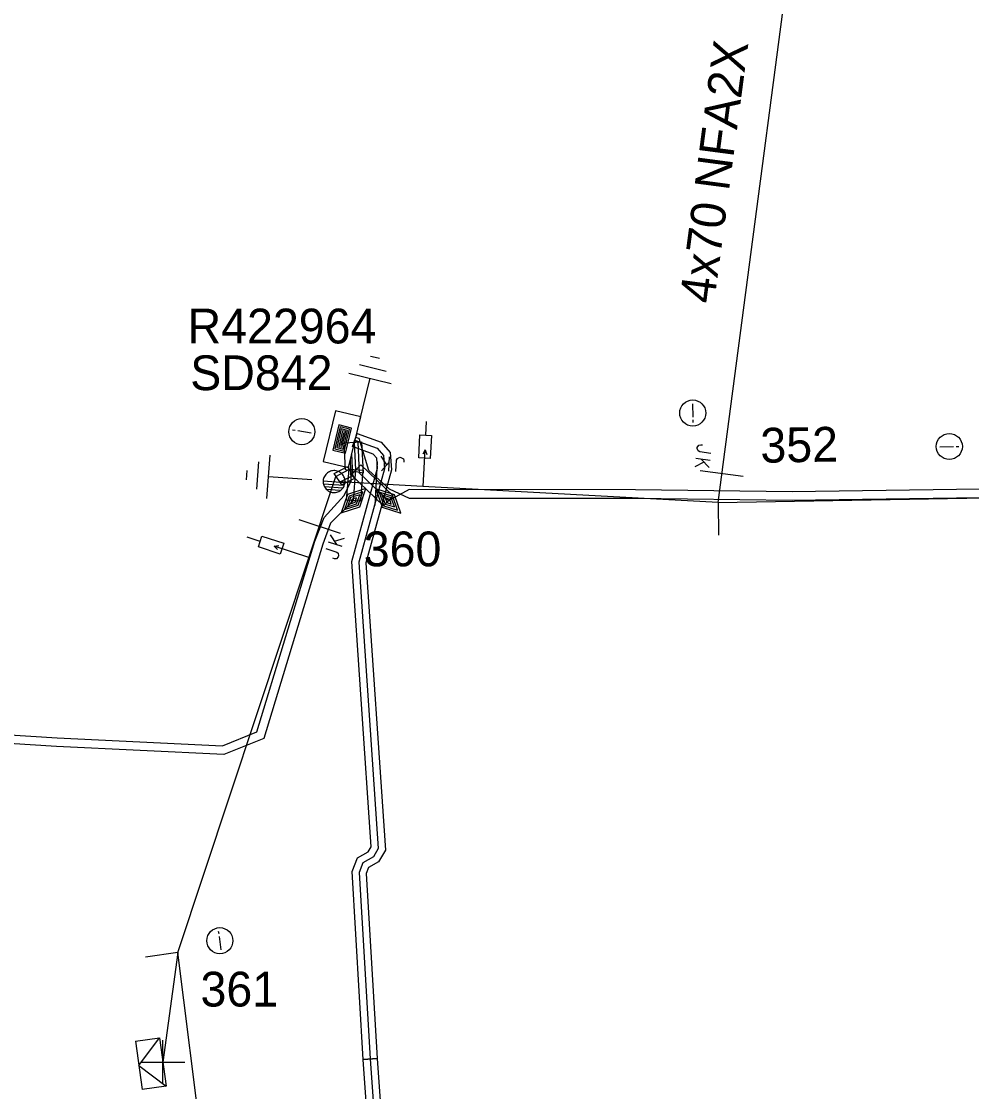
# Model space of a CAD drawing. Extents: x -540466 to -537383, y -1184038 to -1179972.
# Drawn here: x -538053.92 to -538026.6, y -1180873.24 to -1180842.47 of the extents above; entities that cross this region are included whole.
import ezdxf

# ---------------------------------------------------------------- set-up
doc = ezdxf.new("R2010")
doc.units = 0
for name, color, linetype in [('Vrstva 1', 7, 'Continuous'), ('Vrstva 10', 7, 'Continuous'), ('Vrstva 13', 7, 'Continuous'), ('Vrstva 14', 7, 'Continuous'), ('Vrstva 15', 7, 'Continuous'), ('Vrstva 16', 7, 'Continuous'), ('Vrstva 18', 7, 'Continuous'), ('Vrstva 19', 7, 'Continuous'), ('Vrstva 2', 7, 'Continuous'), ('Vrstva 20', 7, 'Continuous'), ('Vrstva 28', 7, 'Continuous'), ('Vrstva 29', 7, 'Continuous'), ('Vrstva 30', 7, 'Continuous'), ('Vrstva 31', 7, 'Continuous'), ('Vrstva 34', 7, 'Continuous'), ('Vrstva 36', 7, 'Continuous'), ('Vrstva 4', 7, 'Continuous'), ('Vrstva 5', 7, 'Continuous'), ('Vrstva 50', 7, 'Continuous'), ('Vrstva 51', 7, 'Continuous'), ('Vrstva 8', 7, 'Continuous'), ('Vrstva 9', 7, 'Continuous')]:
    doc.layers.add(name, color=color, linetype=linetype)

# ---------------------------------------------------------------- blocks, each defined once
blk = doc.blocks.new('NN440')
at = {"layer": 'Vrstva 2'}
for points in [[(0.631, -0.004), (0.627, 0.062), (0.617, 0.127), (0.6, 0.191), (0.577, 0.252), (0.547, 0.311), (0.511, 0.366), (0.469, 0.417), (0.423, 0.464), (0.371, 0.505), (0.316, 0.542), (0.257, 0.571), (0.196, 0.595), (0.132, 0.612), (0.067, 0.622), (0.001, 0.626), (-0.065, 0.622), (-0.13, 0.612), (-0.194, 0.595), (-0.255, 0.571), (-0.314, 0.542), (-0.369, 0.505), (-0.42, 0.464), (-0.467, 0.417), (-0.509, 0.366), (-0.544, 0.311), (-0.574, 0.252), (-0.598, 0.191), (-0.615, 0.127), (-0.626, 0.062), (-0.629, -0.004), (-0.626, -0.07), (-0.615, -0.135), (-0.598, -0.199), (-0.574, -0.26), (-0.544, -0.319), (-0.509, -0.374), (-0.467, -0.426), (-0.42, -0.472), (-0.369, -0.514), (-0.314, -0.55), (-0.255, -0.58), (-0.194, -0.603), (-0.13, -0.62), (-0.065, -0.631), (0.001, -0.634), (0.067, -0.631), (0.132, -0.62), (0.196, -0.603), (0.257, -0.58), (0.316, -0.55), (0.371, -0.514), (0.423, -0.472), (0.469, -0.426), (0.511, -0.374), (0.547, -0.319), (0.577, -0.26), (0.6, -0.199), (0.617, -0.135), (0.627, -0.07), (0.631, -0.004)], [(-0.631, 0), (0.629, 0)], [(-0.601, -0.177), (0.57, -0.177)], [(-0.513, -0.325), (0.501, -0.325)], [(-0.375, -0.473), (0.353, -0.473)]]:
    blk.add_lwpolyline(points, dxfattribs=at)
blk = doc.blocks.new('NN840')
at = {"layer": 'Vrstva 15'}
for points in [[(0.003, 0.619), (0.003, -0.631)], [(-0.538, -0.385), (-0.538, -0.71)], [(-0.332, -0.385), (-0.332, -0.798)], [(-0.332, -0.641), (-0.125, -0.385)], [(-0.263, -0.557), (-0.091, -0.798)], [(-0.745, -0.71), (-0.745, -0.66)], [(-0.73, -0.764), (-0.745, -0.71)], [(-0.657, -0.798), (-0.73, -0.764)], [(-0.627, -0.798), (-0.657, -0.798)], [(-0.558, -0.764), (-0.627, -0.798)], [(-0.538, -0.71), (-0.558, -0.764)]]:
    blk.add_lwpolyline(points, dxfattribs=at)
blk = doc.blocks.new('NN770')
at = {"layer": 'Vrstva 10'}
for p, q in [((0.002, 0.187), (0.002, 0.263)), ((0.002, -0.276), (0.002, 0.111))]:
    blk.add_line(p, q, dxfattribs=at)
blk.add_circle((0, -0.008), 0.375, dxfattribs=at)
blk = doc.blocks.new('NN870')
at = {"layer": 'Vrstva 4'}
for points in [[(0, -0.251), (0.5, 0.001), (0, 0.249), (-0.5, 0.001), (0, -0.251)], [(0.37, -0.003), (0, 0.186), (-0.362, 0.001), (0, -0.188), (0.37, -0.003)], [(0.245, -0.003), (0, 0.123), (-0.252, -0.003), (0, -0.125), (0.245, -0.003)], [(0.122, -0.003), (0, 0.06), (-0.13, -0.003), (0, -0.062), (0.122, -0.003)]]:
    blk.add_lwpolyline(points, dxfattribs=at)
blk = doc.blocks.new('NN800')
at = {"layer": 'Vrstva 1'}
for points in [[(-0.442, 0.442), (0.442, -0.442)], [(-0.442, -0.442), (0.442, 0.442)]]:
    blk.add_lwpolyline(points, dxfattribs=at)
blk = doc.blocks.new('NN820')
at = {"layer": 'Vrstva 13'}
for points in [[(-0.003, 0.004), (-0.003, -1.049)], [(-0.165, -0.813), (0.165, -0.813)], [(-0.165, -1.473), (-0.165, -0.813)], [(0.165, -0.813), (0.165, -1.473)], [(-0.003, -1.049), (-0.062, -0.926)], [(-0.003, -1.049), (0.057, -0.926)], [(0.165, -1.473), (-0.165, -1.473)], [(-0.003, -1.473), (-0.003, -1.871)]]:
    blk.add_lwpolyline(points, dxfattribs=at)
blk = doc.blocks.new('NN620')
at = {"layer": 'Vrstva 8'}
for points in [[(0.752, 0.004), (-0.748, 0.004)], [(-0.748, 0.004), (-0.748, -0.746)], [(0.752, -0.746), (0.752, 0.004)], [(0.368, -0.18), (-0.376, -0.18)], [(-0.376, -0.18), (-0.376, -0.558)], [(0.321, -0.227), (-0.329, -0.227)], [(-0.329, -0.227), (-0.329, -0.51)], [(0.274, -0.274), (-0.281, -0.274)], [(-0.281, -0.274), (-0.281, -0.463)], [(0.274, -0.463), (0.274, -0.274)], [(0.321, -0.51), (0.321, -0.227)], [(0.368, -0.558), (0.368, -0.18)], [(-0.376, -0.558), (0.368, -0.558)], [(-0.329, -0.51), (0.321, -0.51)], [(-0.281, -0.463), (0.274, -0.463)], [(0.227, -0.321), (-0.234, -0.321)], [(-0.234, -0.321), (-0.234, -0.416)], [(-0.234, -0.416), (0.227, -0.416)], [(-0.193, -0.369), (0.185, -0.369)], [(0.227, -0.416), (0.227, -0.321)], [(-0.748, -0.746), (0.752, -0.746)]]:
    blk.add_lwpolyline(points, dxfattribs=at)
blk = doc.blocks.new('NN630')
at = {"layer": 'Vrstva 9'}
for points in [[(-0.003, -0.7), (-0.703, 0)], [(-0.703, -0.7), (-0.703, 0), (0.697, 0), (0.697, -0.7)], [(-0.003, -0.7), (0.697, 0)], [(-0.703, -0.7), (0.697, -0.7)]]:
    blk.add_lwpolyline(points, dxfattribs=at)
blk = doc.blocks.new('NN810')
at = {"layer": 'Vrstva 14'}
for points in [[(0.004, -0.64), (0.004, -1.89)], [(0.629, -1.89), (-0.621, -1.89)], [(0.388, -2.2), (-0.399, -2.2)], [(0.004, -2.515), (-0.124, -2.515)], [(0.137, -2.515), (0.004, -2.515)]]:
    blk.add_lwpolyline(points, dxfattribs=at)
blk = doc.blocks.new('NN510')
at = {"layer": 'Vrstva 2'}
blk.add_lwpolyline([(0.001, 0.002), (0.001, 0.939)], dxfattribs=at)

msp = doc.modelspace()

# ---------------------------------------------------------------- linework, layer by layer
at = {"layer": 'Vrstva 20'}
for points in [[(-538044.262, -1180854.322), (-538043.573, -1180854.57), (-538043.316, -1180854.869), (-538043.278, -1180855.36), (-538044.018, -1180858.04), (-538043.456, -1180866.298), (-538043.654, -1180866.637), (-538043.94, -1180866.799), (-538044.008, -1180866.972), (-538043.69, -1180872.288), (-538044.09, -1180872.312), (-538044.412, -1180866.908), (-538044.26, -1180866.521), (-538043.946, -1180866.343), (-538043.864, -1180866.202), (-538044.422, -1180858), (-538043.682, -1180855.32), (-538043.704, -1180855.031), (-538043.807, -1180854.91), (-538044.398, -1180854.698)], [(-538044.64, -1180854.585), (-538044.139, -1180854.56), (-538044.095, -1180855.457), (-538044.601, -1180855.36)], [(-538044.548, -1180855.267), (-538044.346, -1180855.612), (-538044.706, -1180855.799), (-538044.923, -1180855.469)], [(-538044.101, -1180855.376), (-538044.171, -1180856.266), (-538044.569, -1180856.234), (-538044.499, -1180855.344)], [(-538044.161, -1180855.216), (-538043.231, -1180856.116), (-538043.509, -1180856.404), (-538044.439, -1180855.504)], [(-538043.69, -1180872.286), (-538043.58, -1180873.906), (-538043.98, -1180873.934), (-538044.09, -1180872.314)]]:
    msp.add_lwpolyline(points, close=True, dxfattribs=at)
at = {"layer": 'Vrstva 5'}
for points in [[(-537935.17, -1180854.374), (-537936.98, -1180853.61), (-537941.28, -1180854.35), (-537949.98, -1180854.71), (-537951.472, -1180854.695), (-537960.303, -1180854.845), (-537975.112, -1180855.215), (-537981.461, -1180855.275), (-537989.551, -1180855.315), (-538003.622, -1180855.535), (-538017.592, -1180855.795), (-538031.76, -1180855.995), (-538036.269, -1180855.935), (-538042.769, -1180855.929), (-538043.37, -1180856.26)], [(-538044.37, -1180856.25), (-538044.3, -1180855.36), (-538044.34, -1180854.57)], [(-538043.37, -1180856.26), (-538044.195, -1180855.462), (-538044.239, -1180854.565), (-538044.331, -1180854.535)], [(-538044.33, -1180854.51), (-538043.69, -1180854.74), (-538043.51, -1180854.95), (-538043.48, -1180855.34), (-538044.22, -1180858.02), (-538043.66, -1180866.25), (-538043.8, -1180866.49), (-538044.1, -1180866.66), (-538044.21, -1180866.94), (-538043.89, -1180872.3), (-538043.78, -1180873.92), (-538043.63, -1180875.04), (-538043.4, -1180875.21), (-538042.71, -1180875.13), (-538036.98, -1180874.74), (-538036.48, -1180874.75), (-538035.98, -1180874.87), (-538035.66, -1180875.47), (-538035.43, -1180879.72), (-538034.42, -1180893.47), (-538033.98, -1180901.32), (-538033.83, -1180901.49), (-538033.5, -1180901.52)], [(-538003.89, -1180855.7), (-538004.38, -1180855.7), (-538004.937, -1180855.81), (-538017.588, -1180856.045), (-538031.76, -1180856.245), (-538036.271, -1180856.185), (-538042.759, -1180856.185), (-538043.336, -1180855.916), (-538043.931, -1180855.379), (-538044.204, -1180854.468), (-538044.312, -1180854.436)], [(-538058.503, -1180862.716), (-538052.893, -1180863.065), (-538048.141, -1180863.294), (-538047.152, -1180862.896), (-538045.487, -1180857.416), (-538045.212, -1180856.731), (-538044.64, -1180856.106), (-538044.44, -1180855.683), (-538044.46, -1180855.07)], [(-538044.37, -1180856.25), (-538045.03, -1180856.9), (-538045.253, -1180857.504), (-538046.948, -1180863.084), (-538048.099, -1180863.546), (-538052.907, -1180863.315), (-538058.518, -1180862.968)]]:
    msp.add_lwpolyline(points, dxfattribs=at)
at = {"layer": 'Vrstva 50'}
for points in [[(-538033.892, -1180856.303), (-538031.082, -1180834.986)], [(-538033.892, -1180856.303), (-538042.376, -1180855.84), (-538044.752, -1180855.71), (-538044.392, -1180855.523), (-538044.423, -1180854.907)], [(-538042.079, -1180943.209), (-538042.664, -1180934.986), (-538043.185, -1180927.051), (-538043.722, -1180918.907), (-538044.574, -1180908.527), (-538045.428, -1180899.563), (-538046.397, -1180891.896), (-538047.326, -1180885.914), (-538049.425, -1180869.239), (-538045.657, -1180857.89), (-538044.93, -1180855.7), (-538044.876, -1180855.557), (-538044.501, -1180855.355), (-538044.507, -1180855.235)], [(-538033.892, -1180856.303), (-538026.189, -1180856.168), (-538015.061, -1180856.026), (-537998.972, -1180855.851), (-537981.689, -1180855.628)]]:
    msp.add_lwpolyline(points, dxfattribs=at)
at = {"layer": 'Vrstva 8'}
msp.add_lwpolyline([(-538049.425, -1180869.239), (-538049.85, -1180872.39)], dxfattribs=at)

# ---------------------------------------------------------------- block references
at = {"layer": 'Vrstva 13', "xscale": 0.5, "yscale": 0.5000000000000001, "rotation": -4.318816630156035}
msp.add_blockref('NN440', (-538044.93, -1180855.7), dxfattribs=at)
at = {"layer": 'Vrstva 13'}
for p, rotation in [((-538033.891, -1180856.302), -179.0164779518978), ((-538049.424, -1180869.24), 98.04085553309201)]:
    msp.add_blockref('NN510', p, dxfattribs=dict(at, rotation=rotation))
at = {"layer": 'Vrstva 15'}
for p, rotation in [((-538044.34, -1180854.57), 166.32896115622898), ((-538044.93, -1180855.7), -94.31881669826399)]:
    msp.add_blockref('NN810', p, dxfattribs=dict(at, rotation=rotation))
at = {"layer": 'Vrstva 16'}
for p, rotation in [((-538042.376, -1180855.84), 176.87452230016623), ((-538045.657, -1180857.89), -108.36636383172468)]:
    msp.add_blockref('NN820', p, dxfattribs=dict(at, rotation=rotation))
at = {"layer": 'Vrstva 18'}
for p, rotation in [((-538033.783, -1180855.475), -97.5094138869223), ((-538043.709, -1180855.767), 176.87452230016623), ((-538045.359, -1180856.993), 71.63363610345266)]:
    msp.add_blockref('NN840', p, dxfattribs=dict(at, rotation=rotation))
at = {"layer": 'Vrstva 19'}
for p, rotation in [((-538044.37, -1180856.25), 44.56263601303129), ((-538043.37, -1180856.26), -44.046922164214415)]:
    msp.add_blockref('NN870', p, dxfattribs=dict(at, rotation=rotation))
at = {"layer": 'Vrstva 28', "rotation": -103.6710389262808}
msp.add_blockref('NN620', (-538044.34, -1180854.57), dxfattribs=at)
at = {"layer": 'Vrstva 31', "rotation": -81.95914444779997}
msp.add_blockref('NN630', (-538049.85, -1180872.39), dxfattribs=at)
at = {"layer": 'Vrstva 34', "rotation": 45}
msp.add_blockref('NN800', (-538049.85, -1180872.39), dxfattribs=at)
at = {"layer": 'Vrstva 36'}
for p, rotation in [((-538034.619, -1180853.739), -179.01647781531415), ((-538045.865, -1180854.266), 80.39479724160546), ((-538027.235, -1180854.693), -89.02276667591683), ((-538048.214, -1180868.893), 8.026461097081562)]:
    msp.add_blockref('NN770', p, dxfattribs=dict(at, rotation=rotation))

# ---------------------------------------------------------------- texts
at = {"layer": 'Vrstva 14'}
msp.add_text('352', height=1, rotation=0.984, dxfattribs=at).set_placement((-538032.666, -1180855.162))
for s, p in [('360', (-538044.076, -1180858.138)), ('361', (-538048.77, -1180870.793))]:
    msp.add_text(s, height=1, dxfattribs=at).set_placement(p)
at = {"layer": 'Vrstva 29'}
msp.add_text('R422964', height=1, dxfattribs=at).set_placement((-538049.141, -1180851.731))
at = {"layer": 'Vrstva 30'}
msp.add_text('SD842', height=1, dxfattribs=at).set_placement((-538049.065, -1180853.074))
at = {"layer": 'Vrstva 51'}
msp.add_text('4x70 NFA2X', height=1, rotation=82.491, dxfattribs=at).set_placement((-538034.008, -1180850.612))

doc.saveas('drawing.dxf')
